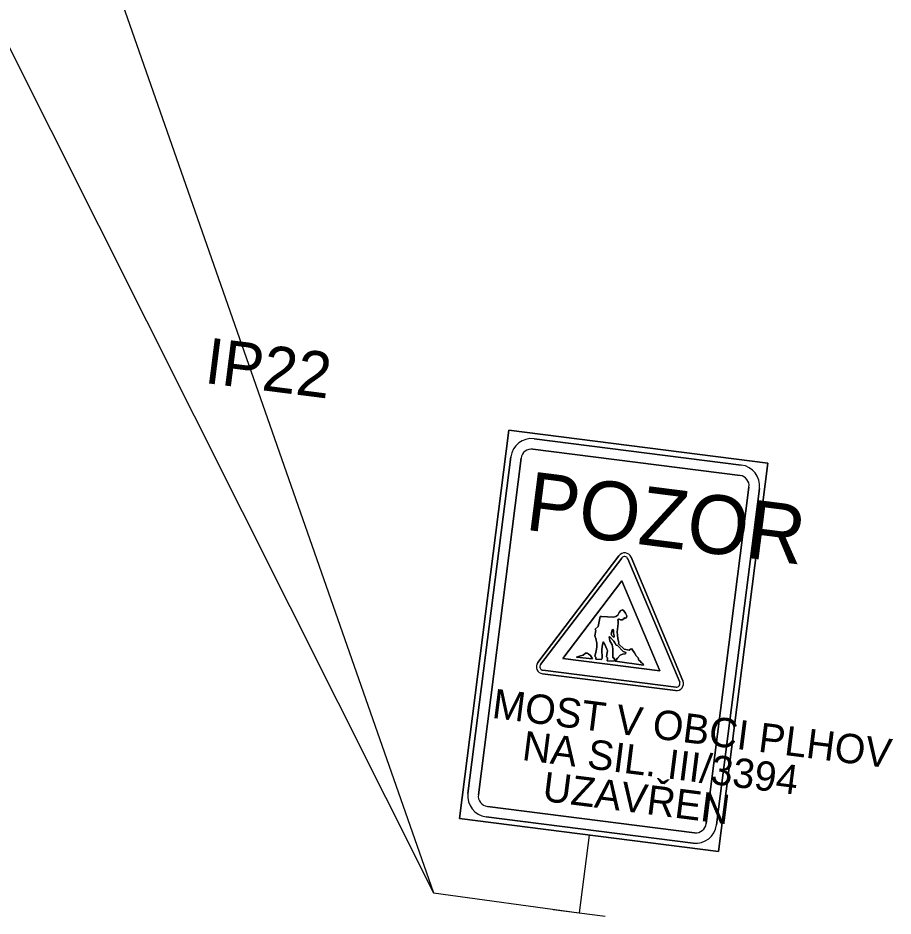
# Model space of a CAD drawing. Extents: x -688893 to -679983, y -1088371 to -1075771.
# Drawn here: x -684417 to -683412, y -1082642 to -1081610 of the extents above; entities that cross this region are included whole.
import ezdxf

# ---------------------------------------------------------------- set-up
doc = ezdxf.new("R2010")
doc.units = 0
for name, color, linetype in [('SDZ', 7, 'Continuous'), ('SDZ ozn', 7, 'Continuous'), ('SDZ plochy', 7, 'Continuous'), ('SDZ symbol', 7, 'Continuous')]:
    doc.layers.add(name, color=color, linetype=linetype)

msp = doc.modelspace()

# ---------------------------------------------------------------- linework, layer by layer
at = {"layer": 'SDZ'}
for p, q in [((-684415.2, -1081256.3), (-683939.8, -1082615.4)), ((-683909.9, -1082530.2), (-683853.2, -1082083.8)), ((-683853.2, -1082083.8), (-683555.6, -1082121.6)), ((-683824.2, -1082093.6), (-683586.1, -1082123.8)), ((-683825.7, -1082105.5), (-683587.6, -1082135.7)), ((-683900.2, -1082501.2), (-683851.1, -1082114.4)), ((-683888.3, -1082502.8), (-683839.1, -1082115.9)), ((-683555.6, -1082121.6), (-683612.3, -1082568)), ((-683577.3, -1082149.1), (-683626.4, -1082536)), ((-683565.3, -1082150.6), (-683614.5, -1082537.5)), ((-683820, -1082350.8), (-683726.7, -1082228)), ((-683723.5, -1082230.7), (-683816.8, -1082353.2)), ((-683723.5, -1082230.6), (-683723.5, -1082230.6)), ((-683656.9, -1082373.5), (-683716.6, -1082231.6)), ((-683712.8, -1082229.8), (-683653.2, -1082372)), ((-683712.8, -1082229.9), (-683712.8, -1082229.9)), ((-683723.4, -1082257.1), (-683791.2, -1082346.3)), ((-683679.9, -1082360.4), (-683723.4, -1082257.1)), ((-683727.9, -1082296.3), (-683730.2, -1082297.9)), ((-683726.3, -1082293.5), (-683727.9, -1082296.3)), ((-683724.6, -1082290.9), (-683726.3, -1082293.5)), ((-683722.8, -1082290.1), (-683724.6, -1082290.9)), ((-683721, -1082291.3), (-683722.8, -1082290.1)), ((-683719.1, -1082294), (-683721, -1082291.3)), ((-683717.6, -1082297.2), (-683719.1, -1082294)), ((-683718.1, -1082299.2), (-683717.6, -1082297.2)), ((-683748.2, -1082298.1), (-683750.8, -1082309.4)), ((-683746.7, -1082297.8), (-683748.2, -1082298.1)), ((-683733.1, -1082298.5), (-683746.7, -1082297.8)), ((-683730.2, -1082297.9), (-683733.1, -1082298.5)), ((-683728.2, -1082309.4), (-683727.7, -1082305.6)), ((-683728, -1082302), (-683727.1, -1082300.9)), ((-683727.8, -1082303.1), (-683728, -1082302)), ((-683727.7, -1082305.6), (-683727.8, -1082303.1)), ((-683727.1, -1082300.9), (-683726.3, -1082301)), ((-683726.3, -1082301), (-683724.8, -1082301.9)), ((-683724.8, -1082301.9), (-683722.9, -1082301.7)), ((-683722.9, -1082301.7), (-683721.3, -1082300.7)), ((-683721.3, -1082300.7), (-683720.2, -1082299.4)), ((-683720.2, -1082299.4), (-683719.2, -1082299.7)), ((-683719.2, -1082299.7), (-683718.1, -1082299.2)), ((-683753.4, -1082313.9), (-683754.4, -1082320.1)), ((-683750.8, -1082309.4), (-683754.1, -1082312.4)), ((-683754.1, -1082312.4), (-683753.4, -1082313.9)), ((-683735.4, -1082316.8), (-683735.8, -1082318.2)), ((-683734.4, -1082313.3), (-683735.4, -1082316.8)), ((-683733.5, -1082312.8), (-683734.4, -1082313.3)), ((-683733, -1082313.9), (-683733.5, -1082312.8)), ((-683732.8, -1082317), (-683733, -1082313.9)), ((-683732.4, -1082320.3), (-683732.8, -1082317)), ((-683728.7, -1082315.6), (-683728.2, -1082309.4)), ((-683728.1, -1082323.1), (-683728.7, -1082315.6)), ((-683754.4, -1082320.1), (-683753.4, -1082323.3)), ((-683753.4, -1082323.3), (-683752, -1082328.4)), ((-683745.7, -1082330), (-683744.9, -1082327.1)), ((-683744.9, -1082327.1), (-683742.8, -1082330)), ((-683738, -1082321.2), (-683737.6, -1082320.8)), ((-683737.2, -1082325.8), (-683738, -1082321.2)), ((-683737.6, -1082320.8), (-683732.6, -1082326.4)), ((-683734.7, -1082330.6), (-683737.2, -1082325.8)), ((-683735.8, -1082318.2), (-683735, -1082319.9)), ((-683735, -1082319.9), (-683732.6, -1082321.9)), ((-683732.6, -1082321.9), (-683732.4, -1082320.3)), ((-683732.6, -1082326.4), (-683731.6, -1082328.3)), ((-683727.3, -1082326.6), (-683728.1, -1082323.1)), ((-683726.9, -1082328.3), (-683727.3, -1082326.6)), ((-683752.8, -1082337.9), (-683754.3, -1082343.4)), ((-683752, -1082332.9), (-683752.8, -1082337.9)), ((-683752, -1082328.4), (-683752, -1082332.9)), ((-683746.4, -1082336), (-683745.7, -1082330)), ((-683746, -1082345.7), (-683746.4, -1082336)), ((-683742.8, -1082330), (-683740.6, -1082335.4)), ((-683740, -1082336.9), (-683741, -1082344.3)), ((-683740.6, -1082335.4), (-683740, -1082336.9)), ((-683733.9, -1082335), (-683734.7, -1082330.6)), ((-683733.9, -1082340.5), (-683733.9, -1082335)), ((-683731.6, -1082328.3), (-683730.1, -1082331)), ((-683730.1, -1082331), (-683728.5, -1082331.2)), ((-683728.5, -1082331.2), (-683722, -1082338.3)), ((-683727.2, -1082329.5), (-683726.9, -1082328.3)), ((-683720.6, -1082335.4), (-683727.2, -1082329.5)), ((-683722, -1082338.3), (-683718.7, -1082339.4)), ((-683715.1, -1082336.6), (-683720.6, -1082335.4)), ((-683713.3, -1082335.4), (-683715.1, -1082336.6)), ((-683712, -1082335.1), (-683713.3, -1082335.4)), ((-683710.6, -1082336.9), (-683712, -1082335.1)), ((-683709, -1082339.8), (-683710.6, -1082336.9)), ((-683791.2, -1082346.3), (-683679.9, -1082360.4)), ((-683771, -1082343.3), (-683775.7, -1082344.6)), ((-683775.7, -1082344.6), (-683757.2, -1082346.5)), ((-683767.9, -1082342.5), (-683771, -1082343.3)), ((-683765.1, -1082340.2), (-683767.9, -1082342.5)), ((-683764.1, -1082339.9), (-683765.1, -1082340.2)), ((-683762.9, -1082340.1), (-683764.1, -1082339.9)), ((-683762, -1082340.8), (-683762.9, -1082340.1)), ((-683759.3, -1082342.6), (-683762, -1082340.8)), ((-683758.2, -1082344.8), (-683759.3, -1082342.6)), ((-683757.2, -1082346.5), (-683758.2, -1082344.8)), ((-683754.3, -1082343.4), (-683753.3, -1082344.8)), ((-683753.3, -1082344.8), (-683753.3, -1082346.8)), ((-683753.3, -1082346.8), (-683746.7, -1082347.4)), ((-683746.7, -1082347.4), (-683746, -1082345.7)), ((-683741, -1082344.3), (-683739.9, -1082345.5)), ((-683739.8, -1082346.5), (-683740.1, -1082348.7)), ((-683740.1, -1082348.7), (-683732.4, -1082349.1)), ((-683739.9, -1082345.5), (-683739.8, -1082346.5)), ((-683733.7, -1082345.2), (-683733.9, -1082340.5)), ((-683731.8, -1082346.3), (-683733.7, -1082345.2)), ((-683732.4, -1082349.1), (-683731.8, -1082347.5)), ((-683731.8, -1082347.5), (-683731.8, -1082346.3)), ((-683728.3, -1082345.9), (-683731, -1082349.4)), ((-683725.2, -1082342.2), (-683728.3, -1082345.9)), ((-683722.6, -1082341.1), (-683725.2, -1082342.2)), ((-683719.3, -1082340.7), (-683722.6, -1082341.1)), ((-683718.7, -1082339.4), (-683719.3, -1082340.7)), ((-683707.1, -1082343.1), (-683709, -1082339.8)), ((-683704.8, -1082345.4), (-683707.1, -1082343.1)), ((-683703.7, -1082348), (-683704.8, -1082345.4)), ((-683702.2, -1082349.2), (-683703.7, -1082348)), ((-683731, -1082349.4), (-683698.5, -1082353.8)), ((-683700.8, -1082351.2), (-683702.2, -1082349.2)), ((-683699.1, -1082352.1), (-683700.8, -1082351.2)), ((-683698.5, -1082353.8), (-683699.1, -1082352.1)), ((-683814.5, -1082363.7), (-683661.7, -1082383.1)), ((-683814.1, -1082359.7), (-683661.1, -1082379.1)), ((-683639.8, -1082546.4), (-683877.9, -1082516.2)), ((-683612.3, -1082568), (-683909.9, -1082530.2)), ((-683641.3, -1082558.3), (-683879.4, -1082528.1)), ((-683761.1, -1082549.1), (-683772.5, -1082638.4)), ((-683802.2, -1082634.7), (-683742.7, -1082642.2))]:
    msp.add_line(p, q, dxfattribs=at)
msp.add_lwpolyline([(-684434.8, -1081628.8), (-683939.8, -1082615.4), (-683772.5, -1082638.4)], dxfattribs=at)
for centre, radius, start, end in [((-683827.2, -1082117.4), 24, 82.7618, 172.7618), ((-683827.2, -1082117.4), 12, 82.7618, 172.7618), ((-683589.2, -1082147.6), 24, 352.7618, 82.7618), ((-683589.2, -1082147.6), 12, 352.7618, 82.7618), ((-683720.3, -1082232.9), 8.1, 22.7309, 142.7927), ((-683720.3, -1082233.1), 4.05, 22.7961, 142.7275), ((-683813.5, -1082355.7), 8.1, 142.7927, 262.7618), ((-683813.6, -1082355.7), 4.05, 142.7275, 262.7618), ((-683660.7, -1082375.1), 8.1, 262.7618, 22.7309), ((-683660.6, -1082375.1), 4.05, 262.7618, 22.7961), ((-683876.4, -1082504.3), 24, 172.7618, 262.7618), ((-683876.4, -1082504.3), 12, 172.7618, 262.7618), ((-683638.3, -1082534.5), 24, 262.7618, 352.7618), ((-683638.3, -1082534.5), 12, 262.7618, 352.7618)]:
    msp.add_arc(centre, radius, start, end, dxfattribs=at)
at = {"layer": 'SDZ plochy'}
for p, q in [((-683853.2, -1082083.8), (-683909.9, -1082530.2)), ((-683555.6, -1082121.6), (-683853.2, -1082083.8)), ((-683586.1, -1082123.8), (-683824.2, -1082093.6)), ((-683824.2, -1082093.6), (-683586.1, -1082123.8)), ((-683825.7, -1082105.5), (-683587.6, -1082135.7)), ((-683587.6, -1082135.7), (-683825.7, -1082105.5)), ((-683851.1, -1082114.4), (-683900.2, -1082501.2)), ((-683900.2, -1082501.2), (-683851.1, -1082114.4)), ((-683888.3, -1082502.8), (-683839.1, -1082115.9)), ((-683839.1, -1082115.9), (-683888.3, -1082502.8)), ((-683612.3, -1082568), (-683555.6, -1082121.6)), ((-683577.3, -1082149.1), (-683626.4, -1082536)), ((-683626.4, -1082536), (-683577.3, -1082149.1)), ((-683614.5, -1082537.5), (-683565.3, -1082150.6)), ((-683565.3, -1082150.6), (-683614.5, -1082537.5)), ((-683820, -1082350.8), (-683726.7, -1082228)), ((-683726.7, -1082228), (-683820, -1082350.8)), ((-683723.5, -1082230.7), (-683816.8, -1082353.2)), ((-683816.8, -1082353.2), (-683723.5, -1082230.7)), ((-683656.9, -1082373.5), (-683716.6, -1082231.6)), ((-683716.6, -1082231.6), (-683656.9, -1082373.5)), ((-683712.8, -1082229.8), (-683653.2, -1082372)), ((-683653.2, -1082372), (-683712.8, -1082229.8)), ((-683791.2, -1082346.3), (-683723.4, -1082257.1)), ((-683723.4, -1082257.1), (-683791.2, -1082346.3)), ((-683723.4, -1082257.1), (-683679.9, -1082360.4)), ((-683679.9, -1082360.4), (-683723.4, -1082257.1)), ((-683727.9, -1082296.3), (-683730.2, -1082297.9)), ((-683730.2, -1082297.9), (-683727.9, -1082296.3)), ((-683726.3, -1082293.5), (-683727.9, -1082296.3)), ((-683727.9, -1082296.3), (-683726.3, -1082293.5)), ((-683724.6, -1082290.9), (-683726.3, -1082293.5)), ((-683726.3, -1082293.5), (-683724.6, -1082290.9)), ((-683722.8, -1082290.1), (-683724.6, -1082290.9)), ((-683724.6, -1082290.9), (-683722.8, -1082290.1)), ((-683721, -1082291.3), (-683722.8, -1082290.1)), ((-683722.8, -1082290.1), (-683721, -1082291.3)), ((-683719.1, -1082294), (-683721, -1082291.3)), ((-683721, -1082291.3), (-683719.1, -1082294)), ((-683717.6, -1082297.2), (-683719.1, -1082294)), ((-683719.1, -1082294), (-683717.6, -1082297.2)), ((-683718.1, -1082299.2), (-683717.6, -1082297.2)), ((-683717.6, -1082297.2), (-683718.1, -1082299.2)), ((-683748.2, -1082298.1), (-683750.8, -1082309.4)), ((-683750.8, -1082309.4), (-683748.2, -1082298.1)), ((-683746.7, -1082297.8), (-683748.2, -1082298.1)), ((-683748.2, -1082298.1), (-683746.7, -1082297.8)), ((-683733.1, -1082298.5), (-683746.7, -1082297.8)), ((-683746.7, -1082297.8), (-683733.1, -1082298.5)), ((-683730.2, -1082297.9), (-683733.1, -1082298.5)), ((-683733.1, -1082298.5), (-683730.2, -1082297.9)), ((-683728.2, -1082309.4), (-683727.7, -1082305.6)), ((-683727.7, -1082305.6), (-683728.2, -1082309.4)), ((-683728, -1082302), (-683727.1, -1082300.9)), ((-683727.1, -1082300.9), (-683728, -1082302)), ((-683727.8, -1082303.1), (-683728, -1082302)), ((-683728, -1082302), (-683727.8, -1082303.1)), ((-683727.7, -1082305.6), (-683727.8, -1082303.1)), ((-683727.8, -1082303.1), (-683727.7, -1082305.6)), ((-683727.1, -1082300.9), (-683726.3, -1082301)), ((-683726.3, -1082301), (-683727.1, -1082300.9)), ((-683726.3, -1082301), (-683724.8, -1082301.9)), ((-683724.8, -1082301.9), (-683726.3, -1082301)), ((-683724.8, -1082301.9), (-683722.9, -1082301.7)), ((-683722.9, -1082301.7), (-683724.8, -1082301.9)), ((-683722.9, -1082301.7), (-683721.3, -1082300.7)), ((-683721.3, -1082300.7), (-683722.9, -1082301.7)), ((-683721.3, -1082300.7), (-683720.2, -1082299.4)), ((-683720.2, -1082299.4), (-683721.3, -1082300.7)), ((-683720.2, -1082299.4), (-683719.2, -1082299.7)), ((-683719.2, -1082299.7), (-683720.2, -1082299.4)), ((-683719.2, -1082299.7), (-683718.1, -1082299.2)), ((-683718.1, -1082299.2), (-683719.2, -1082299.7)), ((-683753.4, -1082313.9), (-683754.4, -1082320.1)), ((-683754.4, -1082320.1), (-683753.4, -1082313.9)), ((-683750.8, -1082309.4), (-683754.1, -1082312.4)), ((-683754.1, -1082312.4), (-683750.8, -1082309.4)), ((-683754.1, -1082312.4), (-683753.4, -1082313.9)), ((-683753.4, -1082313.9), (-683754.1, -1082312.4)), ((-683735.8, -1082318.2), (-683735.4, -1082316.8)), ((-683735.4, -1082316.8), (-683735.8, -1082318.2)), ((-683735.4, -1082316.8), (-683734.4, -1082313.3)), ((-683734.4, -1082313.3), (-683735.4, -1082316.8)), ((-683734.4, -1082313.3), (-683733.5, -1082312.8)), ((-683733.5, -1082312.8), (-683734.4, -1082313.3)), ((-683733.5, -1082312.8), (-683733, -1082313.9)), ((-683733, -1082313.9), (-683733.5, -1082312.8)), ((-683733, -1082313.9), (-683732.8, -1082317)), ((-683732.8, -1082317), (-683733, -1082313.9)), ((-683732.8, -1082317), (-683732.4, -1082320.3)), ((-683732.4, -1082320.3), (-683732.8, -1082317)), ((-683728.7, -1082315.6), (-683728.2, -1082309.4)), ((-683728.2, -1082309.4), (-683728.7, -1082315.6)), ((-683728.1, -1082323.1), (-683728.7, -1082315.6)), ((-683728.7, -1082315.6), (-683728.1, -1082323.1)), ((-683754.4, -1082320.1), (-683753.4, -1082323.3)), ((-683753.4, -1082323.3), (-683754.4, -1082320.1)), ((-683753.4, -1082323.3), (-683752, -1082328.4)), ((-683752, -1082328.4), (-683753.4, -1082323.3)), ((-683745.7, -1082330), (-683744.9, -1082327.1)), ((-683744.9, -1082327.1), (-683745.7, -1082330)), ((-683744.9, -1082327.1), (-683742.8, -1082330)), ((-683742.8, -1082330), (-683744.9, -1082327.1)), ((-683738, -1082321.2), (-683737.6, -1082320.8)), ((-683737.6, -1082320.8), (-683738, -1082321.2)), ((-683737.2, -1082325.8), (-683738, -1082321.2)), ((-683738, -1082321.2), (-683737.2, -1082325.8)), ((-683737.6, -1082320.8), (-683732.6, -1082326.4)), ((-683732.6, -1082326.4), (-683737.6, -1082320.8)), ((-683734.7, -1082330.6), (-683737.2, -1082325.8)), ((-683737.2, -1082325.8), (-683734.7, -1082330.6)), ((-683735, -1082319.9), (-683735.8, -1082318.2)), ((-683735.8, -1082318.2), (-683735, -1082319.9)), ((-683732.6, -1082321.9), (-683735, -1082319.9)), ((-683735, -1082319.9), (-683732.6, -1082321.9)), ((-683732.4, -1082320.3), (-683732.6, -1082321.9)), ((-683732.6, -1082321.9), (-683732.4, -1082320.3)), ((-683732.6, -1082326.4), (-683731.6, -1082328.3)), ((-683731.6, -1082328.3), (-683732.6, -1082326.4)), ((-683727.3, -1082326.6), (-683728.1, -1082323.1)), ((-683728.1, -1082323.1), (-683727.3, -1082326.6)), ((-683726.9, -1082328.3), (-683727.3, -1082326.6)), ((-683727.3, -1082326.6), (-683726.9, -1082328.3)), ((-683752.8, -1082337.9), (-683754.3, -1082343.4)), ((-683754.3, -1082343.4), (-683752.8, -1082337.9)), ((-683752, -1082332.9), (-683752.8, -1082337.9)), ((-683752.8, -1082337.9), (-683752, -1082332.9)), ((-683752, -1082328.4), (-683752, -1082332.9)), ((-683752, -1082332.9), (-683752, -1082328.4)), ((-683746.4, -1082336), (-683745.7, -1082330)), ((-683745.7, -1082330), (-683746.4, -1082336)), ((-683746, -1082345.7), (-683746.4, -1082336)), ((-683746.4, -1082336), (-683746, -1082345.7)), ((-683742.8, -1082330), (-683740.6, -1082335.4)), ((-683740.6, -1082335.4), (-683742.8, -1082330)), ((-683740, -1082336.9), (-683741, -1082344.3)), ((-683741, -1082344.3), (-683740, -1082336.9)), ((-683740.6, -1082335.4), (-683740, -1082336.9)), ((-683740, -1082336.9), (-683740.6, -1082335.4)), ((-683733.9, -1082335), (-683734.7, -1082330.6)), ((-683734.7, -1082330.6), (-683733.9, -1082335)), ((-683733.9, -1082340.5), (-683733.9, -1082335)), ((-683733.9, -1082335), (-683733.9, -1082340.5)), ((-683731.6, -1082328.3), (-683730.1, -1082331)), ((-683730.1, -1082331), (-683731.6, -1082328.3)), ((-683730.1, -1082331), (-683728.5, -1082331.2)), ((-683728.5, -1082331.2), (-683730.1, -1082331)), ((-683728.5, -1082331.2), (-683722, -1082338.3)), ((-683722, -1082338.3), (-683728.5, -1082331.2)), ((-683727.2, -1082329.5), (-683726.9, -1082328.3)), ((-683726.9, -1082328.3), (-683727.2, -1082329.5)), ((-683720.6, -1082335.4), (-683727.2, -1082329.5)), ((-683727.2, -1082329.5), (-683720.6, -1082335.4)), ((-683722, -1082338.3), (-683718.7, -1082339.4)), ((-683718.7, -1082339.4), (-683722, -1082338.3)), ((-683715.1, -1082336.6), (-683720.6, -1082335.4)), ((-683720.6, -1082335.4), (-683715.1, -1082336.6)), ((-683713.3, -1082335.4), (-683715.1, -1082336.6)), ((-683715.1, -1082336.6), (-683713.3, -1082335.4)), ((-683712, -1082335.1), (-683713.3, -1082335.4)), ((-683713.3, -1082335.4), (-683712, -1082335.1)), ((-683710.6, -1082336.9), (-683712, -1082335.1)), ((-683712, -1082335.1), (-683710.6, -1082336.9)), ((-683709, -1082339.8), (-683710.6, -1082336.9)), ((-683710.6, -1082336.9), (-683709, -1082339.8)), ((-683679.9, -1082360.4), (-683791.2, -1082346.3)), ((-683791.2, -1082346.3), (-683679.9, -1082360.4)), ((-683771, -1082343.3), (-683775.7, -1082344.6)), ((-683775.7, -1082344.6), (-683771, -1082343.3)), ((-683775.7, -1082344.6), (-683757.2, -1082346.5)), ((-683757.2, -1082346.5), (-683775.7, -1082344.6)), ((-683767.9, -1082342.5), (-683771, -1082343.3)), ((-683771, -1082343.3), (-683767.9, -1082342.5)), ((-683765.1, -1082340.2), (-683767.9, -1082342.5)), ((-683767.9, -1082342.5), (-683765.1, -1082340.2)), ((-683764.1, -1082339.9), (-683765.1, -1082340.2)), ((-683765.1, -1082340.2), (-683764.1, -1082339.9)), ((-683762.9, -1082340.1), (-683764.1, -1082339.9)), ((-683764.1, -1082339.9), (-683762.9, -1082340.1)), ((-683762, -1082340.8), (-683762.9, -1082340.1)), ((-683762.9, -1082340.1), (-683762, -1082340.8)), ((-683759.3, -1082342.6), (-683762, -1082340.8)), ((-683762, -1082340.8), (-683759.3, -1082342.6)), ((-683758.2, -1082344.8), (-683759.3, -1082342.6)), ((-683759.3, -1082342.6), (-683758.2, -1082344.8)), ((-683757.2, -1082346.5), (-683758.2, -1082344.8)), ((-683758.2, -1082344.8), (-683757.2, -1082346.5)), ((-683754.3, -1082343.4), (-683753.3, -1082344.8)), ((-683753.3, -1082344.8), (-683754.3, -1082343.4)), ((-683753.3, -1082344.8), (-683753.3, -1082346.8)), ((-683753.3, -1082346.8), (-683753.3, -1082344.8)), ((-683753.3, -1082346.8), (-683746.7, -1082347.4)), ((-683746.7, -1082347.4), (-683753.3, -1082346.8)), ((-683746.7, -1082347.4), (-683746, -1082345.7)), ((-683746, -1082345.7), (-683746.7, -1082347.4)), ((-683741, -1082344.3), (-683739.9, -1082345.5)), ((-683739.9, -1082345.5), (-683741, -1082344.3)), ((-683739.8, -1082346.5), (-683740.1, -1082348.7)), ((-683740.1, -1082348.7), (-683739.8, -1082346.5)), ((-683740.1, -1082348.7), (-683732.4, -1082349.1)), ((-683732.4, -1082349.1), (-683740.1, -1082348.7)), ((-683739.9, -1082345.5), (-683739.8, -1082346.5)), ((-683739.8, -1082346.5), (-683739.9, -1082345.5)), ((-683733.7, -1082345.2), (-683733.9, -1082340.5)), ((-683733.9, -1082340.5), (-683733.7, -1082345.2)), ((-683731.8, -1082346.3), (-683733.7, -1082345.2)), ((-683733.7, -1082345.2), (-683731.8, -1082346.3)), ((-683732.4, -1082349.1), (-683731.8, -1082347.5)), ((-683731.8, -1082347.5), (-683732.4, -1082349.1)), ((-683731.8, -1082347.5), (-683731.8, -1082346.3)), ((-683731.8, -1082346.3), (-683731.8, -1082347.5)), ((-683728.3, -1082345.9), (-683731, -1082349.4)), ((-683731, -1082349.4), (-683728.3, -1082345.9)), ((-683725.2, -1082342.2), (-683728.3, -1082345.9)), ((-683728.3, -1082345.9), (-683725.2, -1082342.2)), ((-683722.6, -1082341.1), (-683725.2, -1082342.2)), ((-683725.2, -1082342.2), (-683722.6, -1082341.1)), ((-683719.3, -1082340.7), (-683722.6, -1082341.1)), ((-683722.6, -1082341.1), (-683719.3, -1082340.7)), ((-683718.7, -1082339.4), (-683719.3, -1082340.7)), ((-683719.3, -1082340.7), (-683718.7, -1082339.4)), ((-683707.1, -1082343.1), (-683709, -1082339.8)), ((-683709, -1082339.8), (-683707.1, -1082343.1)), ((-683704.8, -1082345.4), (-683707.1, -1082343.1)), ((-683707.1, -1082343.1), (-683704.8, -1082345.4)), ((-683703.7, -1082348), (-683704.8, -1082345.4)), ((-683704.8, -1082345.4), (-683703.7, -1082348)), ((-683702.2, -1082349.2), (-683703.7, -1082348)), ((-683703.7, -1082348), (-683702.2, -1082349.2)), ((-683731, -1082349.4), (-683698.5, -1082353.8)), ((-683698.5, -1082353.8), (-683731, -1082349.4)), ((-683700.8, -1082351.2), (-683702.2, -1082349.2)), ((-683702.2, -1082349.2), (-683700.8, -1082351.2)), ((-683699.1, -1082352.1), (-683700.8, -1082351.2)), ((-683700.8, -1082351.2), (-683699.1, -1082352.1)), ((-683698.5, -1082353.8), (-683699.1, -1082352.1)), ((-683699.1, -1082352.1), (-683698.5, -1082353.8)), ((-683661.7, -1082383.1), (-683814.5, -1082363.7)), ((-683814.5, -1082363.7), (-683661.7, -1082383.1)), ((-683814.1, -1082359.7), (-683661.1, -1082379.1)), ((-683661.1, -1082379.1), (-683814.1, -1082359.7)), ((-683639.8, -1082546.4), (-683877.9, -1082516.2)), ((-683877.9, -1082516.2), (-683639.8, -1082546.4)), ((-683909.9, -1082530.2), (-683612.3, -1082568)), ((-683879.4, -1082528.1), (-683641.3, -1082558.3)), ((-683641.3, -1082558.3), (-683879.4, -1082528.1))]:
    msp.add_line(p, q, dxfattribs=at)
for centre, radius, start, end in [((-683827.2, -1082117.4), 24, 82.7618, 172.7618), ((-683827.2, -1082117.4), 24, 82.7618, 172.7618), ((-683827.2, -1082117.4), 12, 82.7618, 172.7618), ((-683827.2, -1082117.4), 12, 82.7618, 172.7618), ((-683589.2, -1082147.6), 24, 352.7618, 82.7618), ((-683589.2, -1082147.6), 24, 352.7618, 82.7618), ((-683589.2, -1082147.6), 12, 352.7618, 82.7618), ((-683589.2, -1082147.6), 12, 352.7618, 82.7618), ((-683720.3, -1082232.9), 8.1, 22.7309, 142.7927), ((-683720.3, -1082232.9), 8.1, 22.7309, 142.7927), ((-683720.3, -1082233.1), 4.05, 22.7961, 142.7275), ((-683720.3, -1082233.1), 4.05, 22.7961, 142.7275), ((-683813.5, -1082355.7), 8.1, 142.7927, 262.7618), ((-683813.5, -1082355.7), 8.1, 142.7927, 262.7618), ((-683813.6, -1082355.7), 4.05, 142.7275, 262.7618), ((-683813.6, -1082355.7), 4.05, 142.7275, 262.7618), ((-683660.7, -1082375.1), 8.1, 262.7618, 22.7309), ((-683660.7, -1082375.1), 8.1, 262.7618, 22.7309), ((-683660.6, -1082375.1), 4.05, 262.7618, 22.7961), ((-683660.6, -1082375.1), 4.05, 262.7618, 22.7961), ((-683876.4, -1082504.3), 24, 172.7618, 262.7618), ((-683876.4, -1082504.3), 24, 172.7618, 262.7618), ((-683876.4, -1082504.3), 12, 172.7618, 262.7618), ((-683876.4, -1082504.3), 12, 172.7618, 262.7618), ((-683638.3, -1082534.5), 24, 262.7618, 352.7618), ((-683638.3, -1082534.5), 24, 262.7618, 352.7618), ((-683638.3, -1082534.5), 12, 262.7618, 352.7618), ((-683638.3, -1082534.5), 12, 262.7618, 352.7618)]:
    msp.add_arc(centre, radius, start, end, dxfattribs=at)

# ---------------------------------------------------------------- texts
at = {"layer": 'SDZ ozn'}
msp.add_text('IP22', height=52.5, rotation=352.7618, dxfattribs=at).set_placement((-684204.2, -1082029.3))
at = {"layer": 'SDZ symbol'}
for s, height, p in [('POZOR', 67.5, (-683835.7, -1082198)), ('MOST V OBCI PLHOV', 33.75, (-683873.6, -1082414.3)), ('NA SIL. III/3394', 33.75, (-683839.1, -1082462.7)), ('UZAVŘEN', 33.75, (-683815.7, -1082509.7))]:
    msp.add_text(s, height=height, rotation=352.7618, dxfattribs=at).set_placement(p)

doc.saveas('drawing.dxf')
